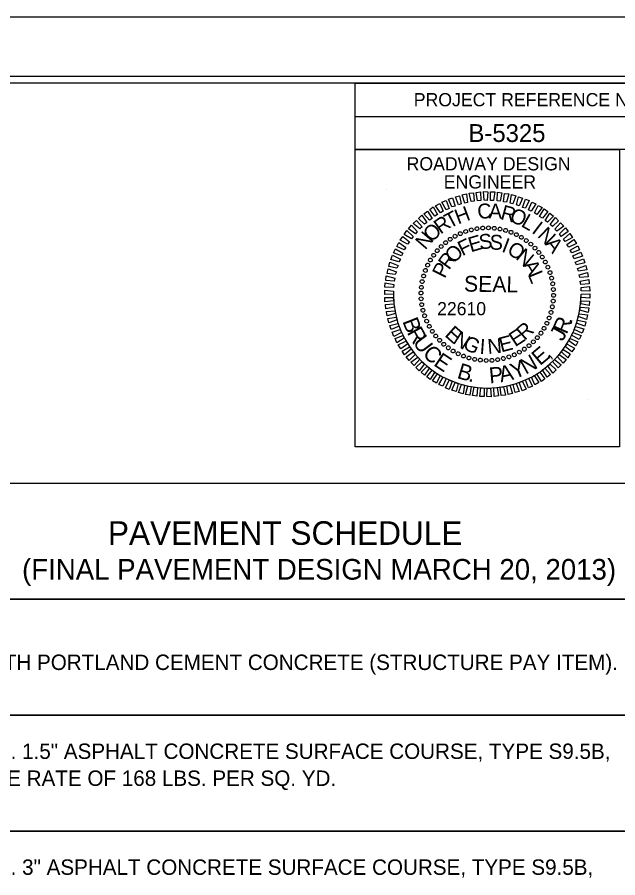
# Model space of a CAD drawing. Extents: x 573732 to 574187, y -53389 to -53257.
# Drawn here: x 573942.92 to 573970.18, y -53296.01 to -53256.95 of the extents above; entities that cross this region are included whole.
import ezdxf

# ---------------------------------------------------------------- set-up
doc = ezdxf.new("R2010")
doc.units = 0
for name, color, linetype in [('Old_Level_19', 7, 'Continuous'), ('Old_Level_21', 7, 'Continuous'), ('Prop Dimension', 7, 'Continuous'), ('Scratch_Level_0', 7, 'Continuous'), ('Sheet Cutting Line CELL', 7, 'Continuous'), ('Sheet Data Field CELL', 7, 'Continuous'), ('Sheet PE Seal CELL', 7, 'Continuous'), ('Sheet Plot Border Inside CELL', 7, 'Continuous'), ('Sheet Plot Border Outside CELL', 7, 'Continuous'), ('Sheet Typical CELL', 7, 'Continuous')]:
    doc.layers.add(name, color=color, linetype=linetype)

msp = doc.modelspace()

# ---------------------------------------------------------------- linework, layer by layer
at = {"layer": 'Old_Level_19'}
msp.add_lwpolyline([(573928.412, -53278.106), (573979.868, -53278.106), (573979.868, -53283.369), (573928.412, -53283.369)], close=True, dxfattribs=at)
for points in [[(573933.675, -53288.632), (573928.412, -53288.632), (573928.412, -53283.369), (573979.867, -53283.369), (573979.867, -53288.632), (573933.675, -53288.632), (573933.675, -53283.369)], [(573933.675, -53293.895), (573928.412, -53293.895), (573928.412, -53288.631), (573979.867, -53288.631), (573979.867, -53293.895), (573933.675, -53293.895), (573933.675, -53288.631)], [(573933.675, -53299.156), (573928.412, -53299.156), (573928.412, -53293.893), (573979.867, -53293.893), (573979.867, -53299.156), (573933.675, -53299.156), (573933.675, -53293.893)]]:
    msp.add_lwpolyline(points, dxfattribs=at)
at = {"layer": 'Scratch_Level_0'}
msp.add_arc((573964.259, -53269.521), 4.26, 180, 360, dxfattribs=at)
at = {"layer": 'Sheet Cutting Line CELL'}
msp.add_line((573984.302, -53256.948), (573782.222, -53256.948), dxfattribs=at)
at = {"layer": 'Sheet PE Seal CELL'}
for p, q in [((573959.687, -53264.757), (573959.687, -53264.757)), ((573963.035, -53266.767), (573963.035, -53266.767)), ((573963.275, -53266.671), (573963.275, -53266.671)), ((573963.527, -53266.599), (573963.527, -53266.599)), ((573963.791, -53266.551), (573963.791, -53266.551)), ((573964.049, -53266.515), (573964.049, -53266.515)), ((573964.313, -53266.509), (573964.313, -53266.509)), ((573964.577, -53266.527), (573964.577, -53266.527)), ((573964.835, -53266.569), (573964.835, -53266.569)), ((573965.087, -53266.623), (573965.087, -53266.623)), ((573965.339, -53266.707), (573965.339, -53266.707)), ((573965.579, -53266.815), (573965.579, -53266.815)), ((573962.363, -53267.175), (573962.363, -53267.175)), ((573962.573, -53267.025), (573962.573, -53267.025)), ((573962.801, -53266.887), (573962.801, -53266.887)), ((573965.813, -53266.935), (573965.813, -53266.935)), ((573966.029, -53267.085), (573966.029, -53267.085)), ((573961.985, -53267.541), (573961.985, -53267.541)), ((573962.165, -53267.355), (573962.165, -53267.355)), ((573966.239, -53267.247), (573966.239, -53267.247)), ((573966.425, -53267.427), (573966.425, -53267.427)), ((573961.673, -53267.967), (573961.673, -53267.967)), ((573961.823, -53267.751), (573961.823, -53267.751)), ((573966.605, -53267.625), (573966.605, -53267.625)), ((573966.755, -53267.835), (573966.755, -53267.835)), ((573961.553, -53268.201), (573961.553, -53268.201)), ((573966.893, -53268.063), (573966.893, -53268.063)), ((573967.013, -53268.297), (573967.013, -53268.297)), ((573961.361, -53268.693), (573961.361, -53268.693)), ((573961.445, -53268.441), (573961.445, -53268.441)), ((573967.109, -53268.537), (573967.109, -53268.537)), ((573961.307, -53268.945), (573961.307, -53268.945)), ((573967.181, -53268.789), (573967.181, -53268.789)), ((573967.229, -53269.053), (573967.229, -53269.053)), ((573961.247, -53269.467), (573961.247, -53269.467)), ((573961.265, -53269.203), (573961.265, -53269.203)), ((573964.259, -53269.521), (573964.259, -53269.521)), ((573967.265, -53269.311), (573967.265, -53269.311)), ((573961.253, -53269.731), (573961.253, -53269.731)), ((573967.253, -53269.839), (573967.253, -53269.839)), ((573967.271, -53269.575), (573967.271, -53269.575)), ((573961.289, -53269.989), (573961.289, -53269.989)), ((573961.337, -53270.253), (573961.337, -53270.253)), ((573967.211, -53270.097), (573967.211, -53270.097)), ((573961.409, -53270.505), (573961.409, -53270.505)), ((573967.073, -53270.601), (573967.073, -53270.601)), ((573967.157, -53270.349), (573967.157, -53270.349)), ((573961.505, -53270.745), (573961.505, -53270.745)), ((573961.625, -53270.979), (573961.625, -53270.979)), ((573966.845, -53271.075), (573966.845, -53271.075)), ((573966.965, -53270.841), (573966.965, -53270.841)), ((573961.763, -53271.207), (573961.763, -53271.207)), ((573961.913, -53271.417), (573961.913, -53271.417)), ((573966.533, -53271.501), (573966.533, -53271.501)), ((573966.695, -53271.291), (573966.695, -53271.291)), ((573962.093, -53271.615), (573962.093, -53271.615)), ((573962.279, -53271.795), (573962.279, -53271.795)), ((573966.155, -53271.867), (573966.155, -53271.867)), ((573966.353, -53271.687), (573966.353, -53271.687)), ((573962.489, -53271.957), (573962.489, -53271.957)), ((573962.705, -53272.107), (573962.705, -53272.107)), ((573962.939, -53272.227), (573962.939, -53272.227)), ((573965.483, -53272.275), (573965.483, -53272.275)), ((573965.717, -53272.155), (573965.717, -53272.155)), ((573965.945, -53272.017), (573965.945, -53272.017)), ((573963.179, -53272.335), (573963.179, -53272.335)), ((573963.431, -53272.419), (573963.431, -53272.419)), ((573963.683, -53272.473), (573963.683, -53272.473)), ((573963.941, -53272.515), (573963.941, -53272.515)), ((573964.205, -53272.533), (573964.205, -53272.533)), ((573964.469, -53272.527), (573964.469, -53272.527)), ((573964.727, -53272.491), (573964.727, -53272.491)), ((573964.991, -53272.443), (573964.991, -53272.443)), ((573965.243, -53272.371), (573965.243, -53272.371)), ((573968.831, -53274.285), (573968.831, -53274.285))]:
    msp.add_line(p, q, dxfattribs=at)
for points in [[(573964.115, -53265.255), (573964.085, -53264.865), (573964.283, -53264.871), (573964.259, -53265.261)], [(573964.403, -53265.261), (573964.403, -53264.871), (573964.601, -53264.877), (573964.547, -53265.267)], [(573962.657, -53265.561), (573962.501, -53265.213), (573962.681, -53265.141), (573962.807, -53265.525)], [(573962.951, -53265.465), (573962.813, -53265.105), (573962.999, -53265.051), (573963.077, -53265.423)], [(573963.239, -53265.387), (573963.113, -53265.009), (573963.317, -53264.967), (573963.365, -53265.357)], [(573963.527, -53265.321), (573963.431, -53264.937), (573963.629, -53264.919), (573963.671, -53265.303)], [(573963.815, -53265.285), (573963.749, -53264.901), (573963.953, -53264.877), (573963.959, -53265.267)], [(573964.703, -53265.279), (573964.727, -53264.889), (573964.925, -53264.925), (573964.847, -53265.303)], [(573964.991, -53265.327), (573965.045, -53264.943), (573965.243, -53264.973), (573965.135, -53265.345)], [(573965.297, -53265.393), (573965.357, -53265.003), (573965.561, -53265.051), (573965.423, -53265.423)], [(573965.585, -53265.471), (573965.675, -53265.099), (573965.861, -53265.159), (573965.711, -53265.513)], [(573965.855, -53265.579), (573965.993, -53265.201), (573966.161, -53265.273), (573965.993, -53265.621)], [(573961.871, -53265.981), (573961.649, -53265.675), (573961.805, -53265.561), (573962.003, -53265.909)], [(573962.135, -53265.831), (573961.913, -53265.507), (573962.099, -53265.411), (573962.249, -53265.759)], [(573962.393, -53265.687), (573962.201, -53265.351), (573962.387, -53265.267), (573962.525, -53265.633)], [(573966.125, -53265.693), (573966.275, -53265.339), (573966.461, -53265.423), (573966.257, -53265.759)], [(573966.401, -53265.831), (573966.563, -53265.489), (573966.743, -53265.591), (573966.515, -53265.903)], [(573966.635, -53265.993), (573966.845, -53265.645), (573967.001, -53265.771), (573966.767, -53266.065)], [(573961.403, -53266.347), (573961.139, -53266.083), (573961.283, -53265.939), (573961.517, -53266.263)], [(573961.643, -53266.161), (573961.385, -53265.873), (573961.547, -53265.747), (573961.757, -53266.083)], [(573966.881, -53266.173), (573967.103, -53265.843), (573967.259, -53265.975), (573966.995, -53266.257)], [(573960.995, -53266.785), (573960.683, -53266.551), (573960.815, -53266.395), (573961.079, -53266.677)], [(573961.205, -53266.557), (573960.899, -53266.311), (573961.049, -53266.173), (573961.301, -53266.461)], [(573967.109, -53266.359), (573967.355, -53266.047), (573967.499, -53266.191), (573967.223, -53266.449)], [(573967.325, -53266.569), (573967.583, -53266.287), (573967.727, -53266.431), (573967.415, -53266.665)], [(573960.815, -53267.013), (573960.491, -53266.809), (573960.605, -53266.635), (573960.893, -53266.899)], [(573967.535, -53266.785), (573967.811, -53266.515), (573967.937, -53266.677), (573967.619, -53266.905)], [(573967.715, -53267.019), (573968.009, -53266.767), (573968.123, -53266.941), (573967.787, -53267.133)], [(573960.491, -53267.511), (573960.149, -53267.361), (573960.239, -53267.175), (573960.563, -53267.397)], [(573960.635, -53267.253), (573960.299, -53267.073), (573960.419, -53266.905), (573960.731, -53267.145)], [(573967.871, -53267.265), (573968.189, -53267.037), (573968.303, -53267.217), (573967.955, -53267.385)], [(573960.371, -53267.787), (573959.999, -53267.649), (573960.089, -53267.463), (573960.431, -53267.655)], [(573968.027, -53267.529), (573968.363, -53267.319), (573968.441, -53267.505), (573968.099, -53267.643)], [(573968.147, -53267.787), (573968.501, -53267.607), (573968.579, -53267.799), (573968.207, -53267.919)], [(573960.251, -53268.051), (573959.879, -53267.943), (573959.957, -53267.757), (573960.317, -53267.925)], [(573968.255, -53268.069), (573968.621, -53267.913), (573968.687, -53268.099), (573968.315, -53268.195)], [(573960.083, -53268.627), (573959.711, -53268.579), (573959.753, -53268.375), (573960.131, -53268.501)], [(573960.161, -53268.339), (573959.789, -53268.261), (573959.831, -53268.063), (573960.209, -53268.213)], [(573968.351, -53268.357), (573968.735, -53268.219), (573968.771, -53268.417), (573968.393, -53268.483)], [(573960.035, -53268.933), (573959.651, -53268.897), (573959.675, -53268.693), (573960.065, -53268.789)], [(573968.423, -53268.645), (573968.801, -53268.531), (573968.837, -53268.735), (573968.459, -53268.771)], [(573960.005, -53269.221), (573959.615, -53269.209), (573959.627, -53269.011), (573960.017, -53269.077)], [(573968.477, -53268.933), (573968.867, -53268.849), (573968.885, -53269.053), (573968.501, -53269.077)], [(573959.999, -53269.521), (573959.609, -53269.539), (573959.609, -53269.335), (573959.999, -53269.377)], [(573968.513, -53269.221), (573968.903, -53269.173), (573968.915, -53269.377), (573968.525, -53269.365)], [(573968.519, -53269.521), (573968.909, -53269.503), (573968.909, -53269.707), (573968.519, -53269.665)], [(573960.005, -53269.821), (573959.615, -53269.869), (573959.603, -53269.665), (573959.993, -53269.677)], [(573968.513, -53269.821), (573968.903, -53269.833), (573968.891, -53270.031), (573968.501, -53269.965)], [(573960.041, -53270.109), (573959.651, -53270.193), (573959.633, -53269.989), (573960.017, -53269.965)], [(573960.095, -53270.397), (573959.717, -53270.511), (573959.681, -53270.307), (573960.059, -53270.271)], [(573968.483, -53270.109), (573968.867, -53270.145), (573968.843, -53270.349), (573968.453, -53270.253)], [(573960.167, -53270.685), (573959.783, -53270.823), (573959.747, -53270.625), (573960.125, -53270.559)], [(573968.357, -53270.703), (573968.729, -53270.781), (573968.687, -53270.979), (573968.309, -53270.829)], [(573968.435, -53270.415), (573968.807, -53270.463), (573968.765, -53270.667), (573968.387, -53270.541)], [(573960.263, -53270.973), (573959.897, -53271.129), (573959.831, -53270.943), (573960.203, -53270.847)], [(573960.371, -53271.255), (573960.017, -53271.435), (573959.939, -53271.243), (573960.311, -53271.123)], [(573968.267, -53270.991), (573968.639, -53271.099), (573968.561, -53271.285), (573968.201, -53271.117)], [(573960.491, -53271.513), (573960.155, -53271.723), (573960.077, -53271.537), (573960.419, -53271.399)], [(573968.147, -53271.255), (573968.519, -53271.393), (573968.429, -53271.579), (573968.087, -53271.387)], [(573960.647, -53271.777), (573960.329, -53272.005), (573960.215, -53271.825), (573960.563, -53271.657)], [(573967.883, -53271.789), (573968.219, -53271.969), (573968.099, -53272.137), (573967.787, -53271.897)], [(573968.027, -53271.531), (573968.369, -53271.681), (573968.279, -53271.867), (573967.955, -53271.645)], [(573960.803, -53272.023), (573960.509, -53272.275), (573960.395, -53272.101), (573960.731, -53271.909)], [(573960.983, -53272.257), (573960.707, -53272.527), (573960.581, -53272.365), (573960.899, -53272.137)], [(573967.523, -53272.257), (573967.835, -53272.491), (573967.703, -53272.647), (573967.439, -53272.365)], [(573967.703, -53272.029), (573968.027, -53272.233), (573967.913, -53272.407), (573967.625, -53272.143)], [(573961.193, -53272.473), (573960.935, -53272.755), (573960.791, -53272.611), (573961.103, -53272.377)], [(573961.409, -53272.683), (573961.163, -53272.995), (573961.019, -53272.851), (573961.295, -53272.593)], [(573967.313, -53272.485), (573967.619, -53272.731), (573967.469, -53272.869), (573967.217, -53272.581)], [(573961.637, -53272.869), (573961.415, -53273.199), (573961.259, -53273.067), (573961.523, -53272.785)], [(573961.883, -53273.049), (573961.673, -53273.397), (573961.517, -53273.271), (573961.751, -53272.977)], [(573966.647, -53273.061), (573966.869, -53273.367), (573966.713, -53273.481), (573966.515, -53273.133)], [(573966.875, -53272.881), (573967.133, -53273.169), (573966.971, -53273.295), (573966.761, -53272.959)], [(573967.115, -53272.695), (573967.379, -53272.959), (573967.235, -53273.103), (573967.001, -53272.779)], [(573962.117, -53273.211), (573961.955, -53273.553), (573961.775, -53273.451), (573962.003, -53273.139)], [(573962.393, -53273.349), (573962.243, -53273.703), (573962.057, -53273.619), (573962.261, -53273.283)], [(573962.663, -53273.463), (573962.525, -53273.841), (573962.357, -53273.769), (573962.525, -53273.421)], [(573966.125, -53273.355), (573966.317, -53273.691), (573966.131, -53273.775), (573965.993, -53273.409)], [(573966.383, -53273.211), (573966.605, -53273.535), (573966.419, -53273.631), (573966.269, -53273.283)], [(573962.933, -53273.571), (573962.843, -53273.943), (573962.657, -53273.883), (573962.807, -53273.529)], [(573963.221, -53273.649), (573963.161, -53274.039), (573962.957, -53273.991), (573963.095, -53273.619)], [(573963.527, -53273.715), (573963.473, -53274.099), (573963.275, -53274.069), (573963.383, -53273.697)], [(573963.815, -53273.763), (573963.791, -53274.153), (573963.593, -53274.117), (573963.671, -53273.739)], [(573964.115, -53273.781), (573964.115, -53274.171), (573963.917, -53274.165), (573963.971, -53273.775)], [(573964.403, -53273.787), (573964.433, -53274.177), (573964.235, -53274.171), (573964.259, -53273.781)], [(573964.703, -53273.757), (573964.769, -53274.141), (573964.565, -53274.165), (573964.559, -53273.775)], [(573964.991, -53273.721), (573965.087, -53274.105), (573964.889, -53274.123), (573964.847, -53273.739)], [(573965.279, -53273.655), (573965.405, -53274.033), (573965.201, -53274.075), (573965.153, -53273.685)], [(573965.567, -53273.577), (573965.705, -53273.937), (573965.519, -53273.991), (573965.441, -53273.619)], [(573965.861, -53273.481), (573966.017, -53273.829), (573965.837, -53273.901), (573965.711, -53273.517)]]:
    msp.add_lwpolyline(points, close=True, dxfattribs=at)
for centre, major_axis in [((573964.049, -53266.519), (-0.006, 0.0862)), ((573964.311, -53266.512), (0.0015, 0.0864)), ((573962.8, -53266.889), (-0.0419, 0.0756)), ((573963.035, -53266.772), (-0.0351, 0.0789)), ((573963.279, -53266.676), (-0.0281, 0.0817)), ((573963.531, -53266.601), (-0.0209, 0.0838)), ((573963.788, -53266.549), (-0.0135, 0.0853)), ((573964.573, -53266.528), (0.009, 0.0859)), ((573964.833, -53266.567), (0.0165, 0.0848)), ((573965.088, -53266.628), (0.0238, 0.0831)), ((573965.337, -53266.711), (0.031, 0.0807)), ((573965.578, -53266.816), (0.0379, 0.0777)), ((573962.365, -53267.182), (-0.0544, 0.0671)), ((573962.576, -53267.026), (-0.0483, 0.0716)), ((573965.809, -53266.941), (0.0445, 0.0741)), ((573966.028, -53267.086), (0.0508, 0.0699)), ((573966.233, -53267.25), (0.0567, 0.0652)), ((573961.987, -53267.547), (-0.0652, 0.0567)), ((573962.168, -53267.356), (-0.06, 0.0622)), ((573966.424, -53267.431), (0.0622, 0.06)), ((573966.598, -53267.627), (0.0671, 0.0544)), ((573961.679, -53267.971), (-0.0741, 0.0445)), ((573961.824, -53267.752), (-0.0699, 0.0508)), ((573966.754, -53267.838), (0.0716, 0.0483)), ((573966.891, -53268.062), (0.0756, 0.0419)), ((573961.449, -53268.443), (-0.0807, 0.031)), ((573961.554, -53268.202), (-0.0777, 0.0379)), ((573967.008, -53268.297), (0.0789, 0.0351)), ((573961.366, -53268.692), (-0.0831, 0.0238)), ((573967.104, -53268.541), (0.0817, 0.0281)), ((573967.179, -53268.793), (0.0838, 0.0209)), ((573961.266, -53269.207), (-0.0859, 0.009)), ((573961.304, -53268.947), (-0.0848, 0.0165)), ((573967.231, -53269.05), (0.0853, 0.0135)), ((573961.249, -53269.469), (-0.0864, 0.0015)), ((573967.261, -53269.311), (0.0862, 0.006)), ((573967.268, -53269.574), (0.0864, -0.0015)), ((573961.256, -53269.731), (-0.0862, -0.006)), ((573961.286, -53269.992), (-0.0853, -0.0135)), ((573967.252, -53269.836), (0.0859, -0.009)), ((573961.338, -53270.249), (-0.0838, -0.0209)), ((573967.152, -53270.351), (0.0831, -0.0238)), ((573967.213, -53270.095), (0.0848, -0.0165)), ((573961.413, -53270.501), (-0.0817, -0.0281)), ((573961.509, -53270.745), (-0.0789, -0.0351)), ((573967.068, -53270.6), (0.0807, -0.031)), ((573961.626, -53270.98), (-0.0756, -0.0419)), ((573961.764, -53271.204), (-0.0716, -0.0483)), ((573966.838, -53271.071), (0.0741, -0.0445)), ((573966.964, -53270.841), (0.0777, -0.0379)), ((573961.92, -53271.415), (-0.0671, -0.0544)), ((573966.53, -53271.496), (0.0652, -0.0567)), ((573966.693, -53271.29), (0.0699, -0.0508)), ((573962.094, -53271.612), (-0.0622, -0.06)), ((573962.284, -53271.793), (-0.0567, -0.0652)), ((573962.49, -53271.956), (-0.0508, -0.0699)), ((573966.153, -53271.86), (0.0544, -0.0671)), ((573966.349, -53271.686), (0.06, -0.0622)), ((573962.709, -53272.101), (-0.0445, -0.0741)), ((573962.939, -53272.226), (-0.0379, -0.0777)), ((573963.18, -53272.331), (-0.031, -0.0807)), ((573965.238, -53272.367), (0.0281, -0.0817)), ((573965.483, -53272.271), (0.0351, -0.0789)), ((573965.718, -53272.153), (0.0419, -0.0756)), ((573965.942, -53272.016), (0.0483, -0.0716)), ((573963.429, -53272.414), (-0.0238, -0.0831)), ((573963.684, -53272.476), (-0.0165, -0.0848)), ((573963.944, -53272.514), (-0.009, -0.0859)), ((573964.206, -53272.53), (-0.0015, -0.0864)), ((573964.469, -53272.523), (0.006, -0.0862)), ((573964.729, -53272.494), (0.0135, -0.0853)), ((573964.987, -53272.441), (0.0209, -0.0838))]:
    msp.add_ellipse(centre, major_axis=major_axis, ratio=0.999708, dxfattribs=at)
at = {"layer": 'Sheet Plot Border Inside CELL'}
msp.add_lwpolyline([(573983.762, -53259.642), (573783.782, -53259.642), (573783.782, -53386.254), (573983.762, -53386.254)], close=True, dxfattribs=at)
at = {"layer": 'Sheet Plot Border Outside CELL'}
msp.add_lwpolyline([(573984.302, -53256.948), (573782.222, -53256.948), (573782.222, -53388.948), (573984.302, -53388.948)], close=True, dxfattribs=at)
at = {"layer": 'Sheet Typical CELL'}
msp.add_line((573958.256, -53261.454), (573982.262, -53261.454), dxfattribs=at)
for points in [[(573982.262, -53259.948), (573802.262, -53259.948), (573802.262, -53385.948), (573982.262, -53385.948)], [(573958.256, -53259.948), (573982.262, -53259.948), (573982.262, -53262.954), (573958.256, -53262.954)], [(573958.256, -53262.954), (573970.262, -53262.954), (573970.262, -53276.454), (573958.256, -53276.454)]]:
    msp.add_lwpolyline(points, close=True, dxfattribs=at)

# ---------------------------------------------------------------- texts
at = {"layer": 'Old_Level_21'}
for s, height, p in [('PAVEMENT SCHEDULE', 1.07198, (573947.04, -53280.899)), ('(FINAL PAVEMENT DESIGN MARCH 20, 2013)', 0.93763, (573943.142, -53282.479)), ('VARIABLE DEPTH PORTLAND CEMENT CONCRETE (STRUCTURE PAY ITEM).', 0.70001, (573935.55, -53286.58)), ('PROP. APPROX. 1.5" ASPHALT CONCRETE SURFACE COURSE, TYPE S9.5B,', 0.70001, (573935.55, -53290.618)), ('AT AN AVERAGE RATE OF 168 LBS. PER SQ. YD. ', 0.70001, (573935.55, -53291.842)), ('PROP. APPROX. 3" ASPHALT CONCRETE SURFACE COURSE, TYPE S9.5B,', 0.70001, (573935.55, -53295.879))]:
    msp.add_text(s, height=height, dxfattribs=at).set_placement(p)
at = {"layer": 'Prop Dimension'}
for s, rotation, p in [('B', 291.4845, (573960.396, -53270.75)), ('R', 66.6114, (573967.863, -53271.376)), ('.', 74.0916, (573968.073, -53270.891)), ('R', 299.1811, (573960.595, -53271.256)), ('J', 61.3535, (573967.677, -53271.698)), ('U', 306.6614, (573960.852, -53271.718)), ('C', 316.599, (573961.283, -53272.273)), ('E', 40.0101, (573966.651, -53272.793)), ('E', 326.1811, (573961.782, -53272.73)), ('N', 29.2842, (573966, -53273.181)), (',', 47.1194, (573967.037, -53272.472)), ('B', 343.4908, (573962.849, -53273.321)), ('Y', 21.3712, (573965.479, -53273.386)), ('P', 5.4216, (573964.37, -53273.573)), ('A', 12.5309, (573964.871, -53273.528)), ('.', 351.1875, (573963.371, -53273.476))]:
    msp.add_text(s, height=0.72, rotation=rotation, dxfattribs=at).set_placement(p)
at = {"layer": 'Sheet Data Field CELL'}
msp.add_text('B-5325', height=0.81, dxfattribs=at).set_placement((573963.407, -53262.612))
at = {"layer": 'Sheet PE Seal CELL'}
for s, height, rotation, p in [('H', 0.677, 20.6195, (573962.933, -53266.359)), ('C', 0.677, 6.2199, (573963.845, -53266.119)), ('A', 0.677, 359.0203, (573964.319, -53266.083)), ('R', 0.677, 344.6211, (573964.823, -53266.107)), ('O', 0.677, 337.4212, (573965.225, -53266.197)), ('R', 0.677, 35.0205, (573962.135, -53266.821)), ('T', 0.677, 27.8198, (573962.543, -53266.557)), ('L', 0.677, 330.2209, (573965.753, -53266.419)), ('O', 0.677, 42.2217, (573961.721, -53267.193)), ('I', 0.677, 323.0201, (573966.239, -53266.707)), ('N', 0.677, 49.4235, (573961.445, -53267.541)), ('E', 0.677, 16.6111, (573963.509, -53267.625)), ('S', 0.677, 7.2556, (573963.923, -53267.499)), ('S', 0.677, 357.9004, (573964.355, -53267.493)), ('N', 0.677, 315.8189, (573966.497, -53266.893)), ('F', 0.677, 25.967, (573963.125, -53267.805)), ('I', 0.677, 339.1896, (573964.871, -53267.577)), ('O', 0.677, 329.8335, (573965.111, -53267.661)), ('A', 0.677, 308.6172, (573966.851, -53267.247)), ('O', 0.677, 44.6812, (573962.729, -53268.159)), ('N', 0.677, 320.4766, (573965.513, -53267.901)), ('R', 0.677, 54.0397, (573962.519, -53268.453)), ('P', 0.677, 63.3989, (573962.327, -53268.837)), ('A', 0.677, 301.7603, (573965.855, -53268.213)), ('SEAL', 0.7198, 359, (573963.197, -53269.401)), ('L', 0.677, 292.4008, (573966.089, -53268.627)), ('E', 0.677, 318.2769, (573962.291, -53271.399)), ('E', 0.677, 33.1241, (573965.525, -53271.933)), ('R', 0.677, 42.4814, (573965.951, -53271.651)), ('N', 0.677, 327.634, (573962.651, -53271.723)), ('G', 0.677, 336.9902, (573963.107, -53271.993)), ('N', 0.677, 5.0564, (573964.295, -53272.239)), ('E', 0.677, 14.4118, (573964.889, -53272.167)), ('I', 0.677, 355.7012, (573963.893, -53272.221))]:
    msp.add_text(s, height=height, rotation=rotation, dxfattribs=at).set_placement(p)
msp.add_text('   22610  ', height=0.597, dxfattribs=at).set_placement((573961.318, -53270.476))
at = {"layer": 'Sheet Typical CELL'}
for s, height, p in [('PROJECT REFERENCE NO.', 0.60001, (573960.92, -53260.992)), ('ROADWAY DESIGN', 0.60001, (573960.596, -53263.902)), ('ENGINEER', 0.6, (573962.282, -53264.724))]:
    msp.add_text(s, height=height, dxfattribs=at).set_placement(p)

doc.saveas('drawing.dxf')
